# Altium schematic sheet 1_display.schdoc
size 309 x 223 mm; Symbol: Sheet-Symbol_A4; Device: Sheet-Symbol_A4; Company: Chaoticvolt; Drawed: Robin; Reviewed: Robin; Version: V0.1; Page Size: A4; @Project Name: Chaoticvolt-4 digit 7seg display; @Page Count: 1; @Update Date: 2024-12-22; @Create Date: 2023-04-09; @Schematic Name: 4 digit 7seg display; Part Number: NTOCLOCKPCB-002; @Page No: 1; @Page Name: display; @Board Name: 4 digit 7seg display; @Create Time: 11:39:03; @Update Time: 17:40:40
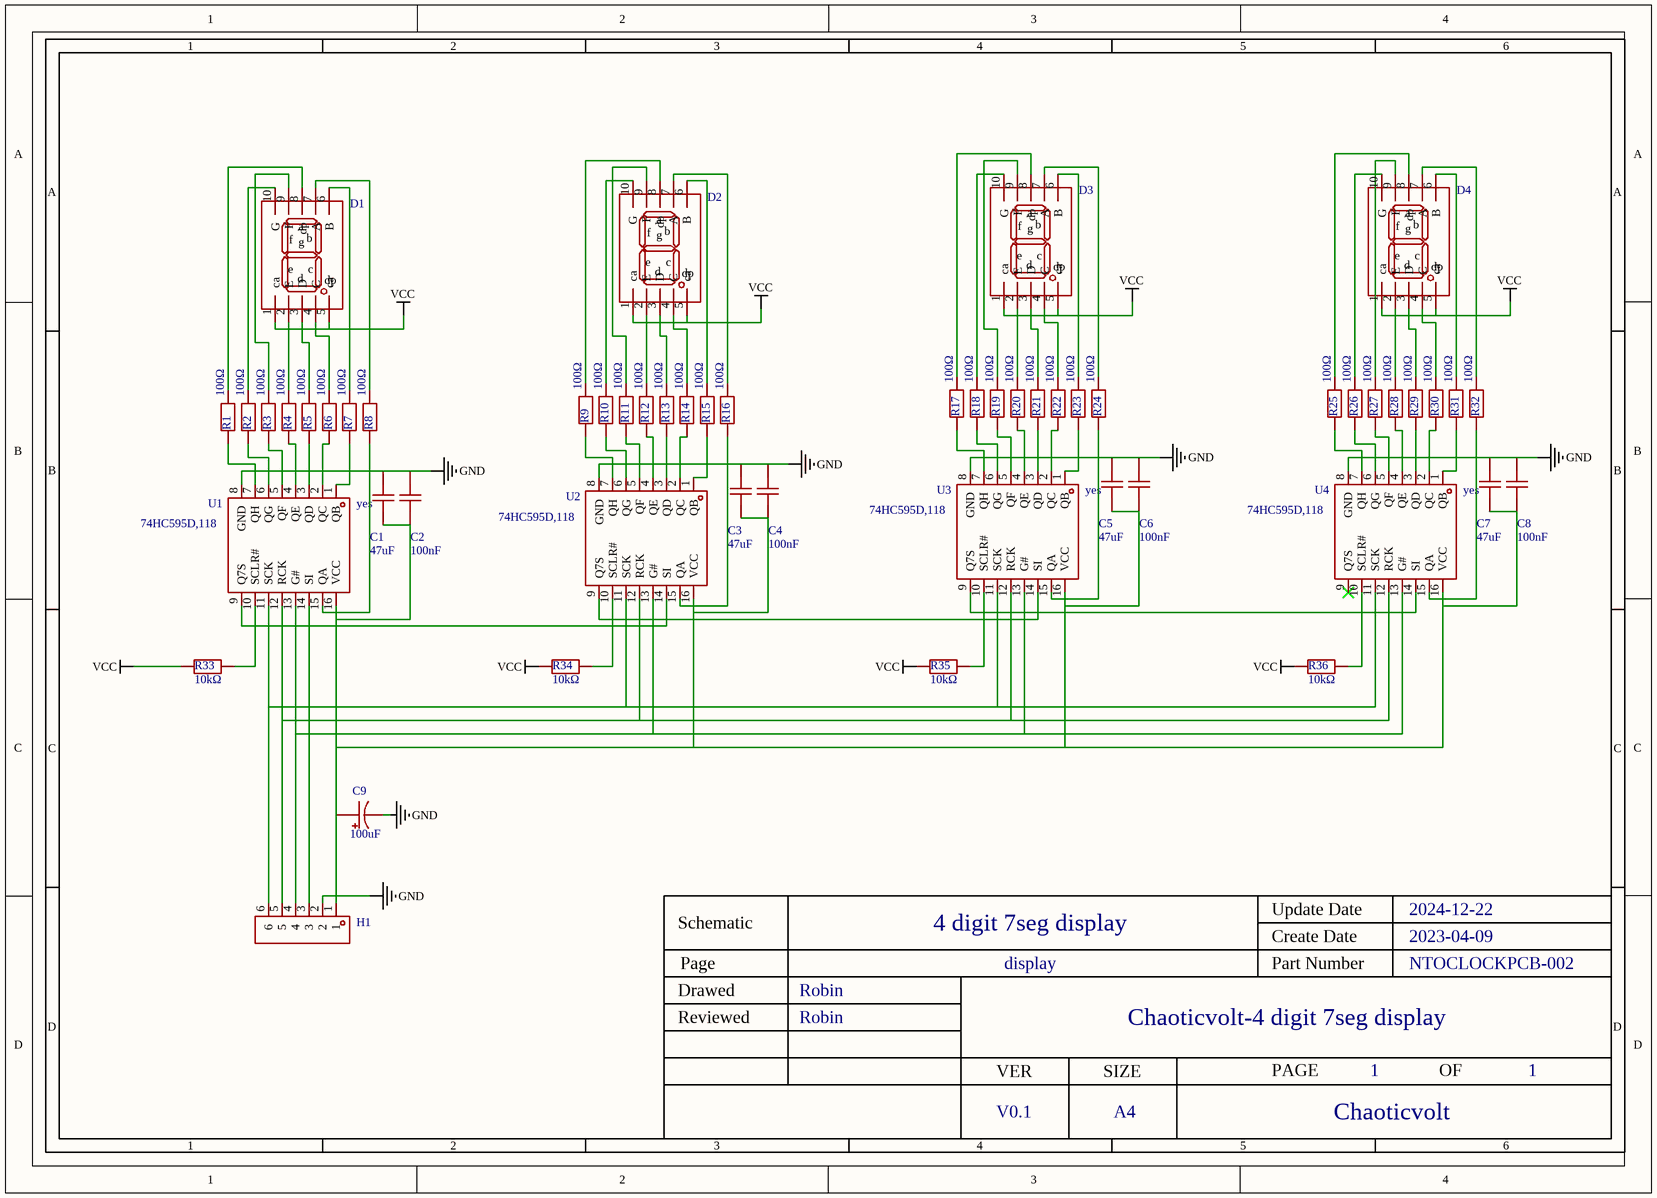
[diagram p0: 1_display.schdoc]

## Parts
C1  47uF  [C1206]  (value not drawn)
C2  100nF  [C0402_NEW]  (value not drawn)
C3  47uF  [C1206]  (value not drawn)
C4  100nF  [C0402_NEW]  (value not drawn)
C5  47uF  [C1206]  (value not drawn)
C6  100nF  [C0402_NEW]  (value not drawn)
C7  47uF  [C1206]  (value not drawn)
C8  100nF  [C0402_NEW]  (value not drawn)
C9  100uF  [CAP-SMD_L3.5-W2.8-R-RD]  (value not drawn)
D1  FJS12101  [FJS12101]  (value not drawn)
D2  FJS12101  [FJS12101]  (value not drawn)
D3  FJS12101  [FJS12101]  (value not drawn)
D4  FJS12101  [FJS12101]  (value not drawn)
H1  PZ254R-11-06P  [HDR-TH_6P-P2.54-V_Z-211-0611-0021-001]  (value not drawn)
R1  100Ω  [R0805]  (value not drawn)
R2  100Ω  [R0805]  (value not drawn)
R3  100Ω  [R0805]  (value not drawn)
R4  100Ω  [R0805]  (value not drawn)
R5  100Ω  [R0805]  (value not drawn)
R6  100Ω  [R0805]  (value not drawn)
R7  100Ω  [R0805]  (value not drawn)
R8  100Ω  [R0805]  (value not drawn)
R9  100Ω  [R0805]  (value not drawn)
R10  100Ω  [R0805]  (value not drawn)
R11  100Ω  [R0805]  (value not drawn)
R12  100Ω  [R0805]  (value not drawn)
R13  100Ω  [R0805]  (value not drawn)
R14  100Ω  [R0805]  (value not drawn)
R15  100Ω  [R0805]  (value not drawn)
R16  100Ω  [R0805]  (value not drawn)
R17  100Ω  [R0805]  (value not drawn)
R18  100Ω  [R0805]  (value not drawn)
R19  100Ω  [R0805]  (value not drawn)
R20  100Ω  [R0805]  (value not drawn)
R21  100Ω  [R0805]  (value not drawn)
R22  100Ω  [R0805]  (value not drawn)
R23  100Ω  [R0805]  (value not drawn)
R24  100Ω  [R0805]  (value not drawn)
R25  100Ω  [R0805]  (value not drawn)
R26  100Ω  [R0805]  (value not drawn)
R27  100Ω  [R0805]  (value not drawn)
R28  100Ω  [R0805]  (value not drawn)
R29  100Ω  [R0805]  (value not drawn)
R30  100Ω  [R0805]  (value not drawn)
R31  100Ω  [R0805]  (value not drawn)
R32  100Ω  [R0805]  (value not drawn)
R33  10kΩ  [R0805]  (value not drawn)
R34  10kΩ  [R0805]  (value not drawn)
R35  10kΩ  [R0805]  (value not drawn)
R36  10kΩ  [R0805]  (value not drawn)
U1  Add into BOM: yes  [SOIC-16_L9.9-W3.9-P1.27-LS6.0-BL]  (hidden comment: 74HC595D,118)
U2  74HC595D,118  [SOIC-16_L9.9-W3.9-P1.27-LS6.0-BL]  (value not drawn)
U3  Add into BOM: yes  [SOIC-16_L9.9-W3.9-P1.27-LS6.0-BL]  (hidden comment: 74HC595D,118)
U4  Add into BOM: yes  [SOIC-16_L9.9-W3.9-P1.27-LS6.0-BL]  (hidden comment: 74HC595D,118)

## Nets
GND: C1.2 C2.2 C3.2 C4.2 C5.2 C6.2 C7.2 C8.2 C9.2 H1.2 U1.8(GND) U2.8(GND) U3.8(GND) U4.8(GND)
VCC: D1.1(ca) D1.5(ca) D2.1(ca) D2.5(ca) D3.1(ca) D3.5(ca) D4.1(ca) D4.5(ca) R33.2 R34.2 R35.2 R36.2
NetC1_1: C1.1 C2.1 C3.1 C4.1 C5.1 C6.1 C7.1 C8.1 C9.1 H1.1 U1.16(VCC) U2.16(VCC) U3.16(VCC) U4.16(VCC)
NetD1_2: D1.2(E) R4.1
NetD1_3: D1.3(D) R5.1
NetD1_4: D1.4(C) R6.1
NetD1_6: D1.6(B) R7.1
NetD1_7: D1.7(A) R8.1
NetD1_8: D1.8(dp) R1.1
NetD1_9: D1.9(F) R3.1
NetD1_10: D1.10(G) R2.1
NetD2_2: D2.2(E) R12.1
NetD2_3: D2.3(D) R13.1
NetD2_4: D2.4(C) R14.1
NetD2_6: D2.6(B) R15.1
NetD2_7: D2.7(A) R16.1
NetD2_8: D2.8(dp) R9.1
NetD2_9: D2.9(F) R11.1
NetD2_10: D2.10(G) R10.1
NetD3_2: D3.2(E) R20.1
NetD3_3: D3.3(D) R21.1
NetD3_4: D3.4(C) R22.1
NetD3_6: D3.6(B) R23.1
NetD3_7: D3.7(A) R24.1
NetD3_8: D3.8(dp) R17.1
NetD3_9: D3.9(F) R19.1
NetD3_10: D3.10(G) R18.1
NetD4_2: D4.2(E) R28.1
NetD4_3: D4.3(D) R29.1
NetD4_4: D4.4(C) R30.1
NetD4_6: D4.6(B) R31.1
NetD4_7: D4.7(A) R32.1
NetD4_8: D4.8(dp) R25.1
NetD4_9: D4.9(F) R27.1
NetD4_10: D4.10(G) R26.1
NetH1_3: H1.3 U1.14(SI)
NetH1_4: H1.4 U1.13(G#) U2.13(G#) U3.13(G#) U4.13(G#)
NetH1_5: H1.5 U1.12(RCK) U2.12(RCK) U3.12(RCK) U4.12(RCK)
NetH1_6: H1.6 U1.11(SCK) U2.11(SCK) U3.11(SCK) U4.11(SCK)
NetR1_2: R1.2 U1.7(QH)
NetR2_2: R2.2 U1.6(QG)
NetR3_2: R3.2 U1.5(QF)
NetR4_2: R4.2 U1.4(QE)
NetR5_2: R5.2 U1.3(QD)
NetR6_2: R6.2 U1.2(QC)
NetR7_2: R7.2 U1.1(QB)
NetR8_2: R8.2 U1.15(QA)
NetR9_2: R9.2 U2.7(QH)
NetR10_2: R10.2 U2.6(QG)
NetR11_2: R11.2 U2.5(QF)
NetR12_2: R12.2 U2.4(QE)
NetR13_2: R13.2 U2.3(QD)
NetR14_2: R14.2 U2.2(QC)
NetR15_2: R15.2 U2.1(QB)
NetR16_2: R16.2 U2.15(QA)
NetR17_2: R17.2 U3.7(QH)
NetR18_2: R18.2 U3.6(QG)
NetR19_2: R19.2 U3.5(QF)
NetR20_2: R20.2 U3.4(QE)
NetR21_2: R21.2 U3.3(QD)
NetR22_2: R22.2 U3.2(QC)
NetR23_2: R23.2 U3.1(QB)
NetR24_2: R24.2 U3.15(QA)
NetR25_2: R25.2 U4.7(QH)
NetR26_2: R26.2 U4.6(QG)
NetR27_2: R27.2 U4.5(QF)
NetR28_2: R28.2 U4.4(QE)
NetR29_2: R29.2 U4.3(QD)
NetR30_2: R30.2 U4.2(QC)
NetR31_2: R31.2 U4.1(QB)
NetR32_2: R32.2 U4.15(QA)
NetR33_1: R33.1 U1.10(SCLR#)
NetR34_1: R34.1 U2.10(SCLR#)
NetR35_1: R35.1 U3.10(SCLR#)
NetR36_1: R36.1 U4.10(SCLR#)
NetU1_9: U1.9(Q7S) U2.14(SI)
NetU2_9: U2.9(Q7S) U3.14(SI)
NetU3_9: U3.9(Q7S) U4.14(SI)

Not connected (* = marked no-connect by the designer): U4 9(Q7S)*

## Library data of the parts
C1 C3 C5 C7 = CL31A476MPHNNNE: Capacitance: Tolerance:±20% Tolerance:±20% Voltage Rated: Temperature Coefficient:; Manufacturer: SAMSUNG(三星); Add into BOM: yes; Tolerance: ±20%
C2 C4 C6 C8 = CL05B104KO5NNNC: Capacitance: Tolerance:±10% Tolerance:±10% Voltage Rated: Temperature Coefficient:; Manufacturer: SAMSUNG(三星); Symbol: C1210C104K1RAC7800; Add into BOM: yes; Tolerance: ±10%
C9 = CA45-B-10V-100uF-M: Capacitance: Tolerance:±20% Tolerance:±20% Rated Voltage: Equivalent Series Resistance(ESR):4Ω@100kHz Operating Temperature:-55℃~+125℃ Operating Temperature:-55℃~+125℃; Manufacturer: CEC(振华新云); Add into BOM: yes; Tolerance: ±20%
D1-D4 = FJS12101: Add into BOM: yes
H1 = PZ254R-11-06P: Pitch:2.54mm Number of Pins:6 Number of Rows: Pin Structure:1x6P Row Spacing:- Mounting Type:Shrouded Circluar Pins/Square Pins:Square Pins Current Rating (Max):- Voltage Rating (Max):- Length of Mating Pin:6mm Insulation Height:2.5mm Contact Material: Contact Plating:- Operating Temperature Range:-40~+105 Operating Temperature Range:-40~+105 Color:Black; Manufacturer: XFCN(兴飞); Add into BOM: no; Convert to PCB: yes; Pitch: 2.54mm; Pin Structure: 1x6P
R1-R32 = 0805W8F1000T5E_C17408: Type:Thick Film Resistors Resistance: Tolerance:±1% Tolerance:±1% Power(Watts): Temperature Coefficient:±100ppm/℃ Temperature Coefficient:±100ppm/℃ Overload Voltage (Max): Operating Temperature Range:-55℃~+155℃ Operating Temperature Range:-55℃~+155℃; Manufacturer: UNI-ROYAL(厚声); Symbol: RK73H2ETTD2700F; Add into BOM: yes; Tolerance: ±1%
R33-R36 = 0805W8F1002T5E: Type:Thick Film Resistors Resistance: Tolerance:±1% Tolerance:±1% Power(Watts): Temperature Coefficient:±100ppm/℃ Temperature Coefficient:±100ppm/℃ Overload Voltage (Max): Operating Temperature Range:-55℃~+155℃ Operating Temperature Range:-55℃~+155℃; Manufacturer: UNI-ROYAL(厚声); Symbol: RK73H2ETTD1002F; Add into BOM: yes; Tolerance: ±1%
U1 U3 U4 = 74HC595D,118: Series: Logic Type:ShiftRegister Output Type:Tri-State Function:Serial to parallel, serial Voltage - Supply:2V~6V Voltage - Supply:2V~6V Operating Temperature:-40℃~+125℃ Operating Temperature:-40℃~+125℃; Manufacturer: Nexperia(安世); Symbol: 74HC595D_C431479; Voltage - Supply: 2V~6V
U2 = 74HC595D,118: Series: Logic Type:ShiftRegister Output Type:Tri-State Function:Serial to parallel, serial Voltage - Supply:2V~6V Voltage - Supply:2V~6V Operating Temperature:-40℃~+125℃ Operating Temperature:-40℃~+125℃; Manufacturer: Nexperia(安世); Symbol: 74HC595D_C431479; Add into BOM: yes; Voltage - Supply: 2V~6V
